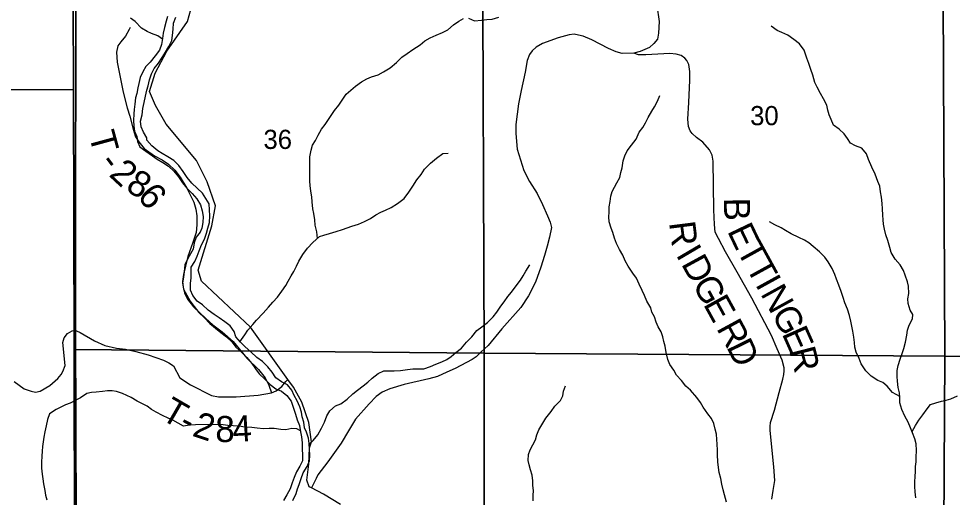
# Model space of a CAD drawing. Extents: x 2043100 to 2470832, y 443715 to 810583.
# Drawn here: x 2290243 to 2300993, y 612140 to 617648 of the extents above; entities that cross this region are included whole.
import ezdxf

# ---------------------------------------------------------------- set-up
doc = ezdxf.new("R2010")
doc.units = 0
for name, color, linetype in [('GM_X_County_Road', 7, 'Continuous'), ('GM_X_Major_River', 7, 'Continuous'), ('GM_X_Minor_River', 7, 'Continuous'), ('GM_X_Section', 7, 'Continuous'), ('GM_X_Section_Text', 7, 'Continuous'), ('GM_X_State_Route', 7, 'Continuous'), ('GM_X_Township', 7, 'Continuous'), ('GM_X_Township_Road', 7, 'Continuous'), ('GM_X_Township_Road_Text', 7, 'Continuous')]:
    doc.layers.add(name, color=color, linetype=linetype)

msp = doc.modelspace()

# ---------------------------------------------------------------- linework, layer by layer
at = {"layer": 'GM_X_County_Road'}
msp.add_lwpolyline([(2297592, 617800), (2297616, 617614), (2297611, 617482), (2297600, 617413), (2297558, 617363), (2297505, 617316), (2297399, 617271), (2297326, 617253), (2297192, 617247), (2297121, 617265), (2297035, 617304), (2296844, 617405), (2296742, 617446), (2296687, 617459), (2296639, 617471), (2296583, 617464), (2296456, 617427), (2296274, 617363), (2296203, 617321), (2296157, 617280), (2296126, 617236), (2296096, 617167), (2296074, 617033), (2296028, 616822), (2295999, 616667), (2295967, 616432), (2295969, 616326), (2295984, 616148), (2296061, 615900), (2296126, 615774), (2296211, 615637), (2296273, 615511), (2296332, 615381), (2296363, 615305), (2296377, 615245), (2296356, 615133), (2296327, 615030), (2296296, 614922), (2296256, 614787), (2296193, 614616), (2296115, 614457), (2296024, 614326), (2295805, 614078), (2295647, 613888), (2295563, 613809), (2295510, 613756), (2295464, 613724), (2295269, 613624), (2295174, 613581), (2295064, 613530), (2294966, 613503), (2294681, 613440), (2294515, 613390), (2294428, 613351), (2294360, 613299), (2294277, 613216), (2294123, 613038), (2294042, 612905), (2293958, 612762), (2293802, 612548), (2293727, 612447), (2293689, 612397), (2293669, 612358), (2293615, 612247)], dxfattribs=at)
at = {"layer": 'GM_X_Major_River'}
for points in [[(2291958, 617674), (2291942, 617619), (2291921, 617547), (2291908, 617481), (2291901, 617419), (2291889, 617352), (2291864, 617286), (2291813, 617219), (2291756, 617149), (2291706, 617098), (2291671, 617036), (2291644, 616971), (2291626, 616903), (2291617, 616853)], [(2291652, 616402), (2291647, 616470), (2291664, 616542), (2291674, 616615), (2291687, 616685), (2291704, 616757), (2291719, 616826), (2291733, 616876), (2291748, 616946), (2291773, 617013), (2291804, 617075), (2291852, 617136), (2291897, 617200), (2291934, 617261), (2291974, 617327), (2292005, 617396), (2292014, 617456), (2292023, 617526), (2292027, 617598), (2292052, 617667)], [(2291617, 616853), (2291604, 616786), (2291590, 616736), (2291579, 616666), (2291572, 616602), (2291570, 616552), (2291567, 616475), (2291570, 616411), (2291577, 616355), (2291605, 616293), (2291610, 616235), (2291640, 616172), (2291709, 616122), (2291785, 616071), (2291838, 616031), (2291902, 615994), (2291967, 615949), (2292031, 615895), (2292084, 615828), (2292128, 615758), (2292179, 615698), (2292242, 615635), (2292296, 615575), (2292335, 615506), (2292356, 615436), (2292368, 615370), (2292363, 615301), (2292354, 615237), (2292332, 615191), (2292288, 615133)], [(2291717, 616275), (2291681, 616342), (2291652, 616402)], [(2293401, 612103), (2293438, 612185), (2293454, 612236), (2293473, 612288), (2293494, 612358), (2293520, 612423), (2293565, 612493), (2293590, 612558), (2293595, 612626), (2293593, 612692), (2293586, 612760), (2293581, 612820), (2293558, 612888), (2293536, 612940), (2293527, 613004), (2293507, 613066), (2293500, 613118), (2293479, 613180), (2293449, 613249), (2293416, 613311), (2293387, 613371), (2293337, 613434), (2293270, 613468), (2293204, 613513), (2293161, 613581), (2293111, 613642), (2293050, 613704), (2292984, 613747), (2292915, 613813), (2292852, 613872), (2292796, 613924), (2292745, 613987), (2292725, 614047), (2292678, 614115), (2292617, 614160), (2292553, 614205), (2292493, 614243), (2292424, 614294), (2292360, 614356), (2292297, 614397), (2292247, 614463), (2292222, 614525), (2292221, 614599), (2292228, 614667), (2292230, 614737), (2292231, 614787), (2292270, 614852), (2292300, 614914), (2292323, 614976), (2292348, 615045), (2292381, 615111), (2292405, 615178), (2292422, 615236), (2292439, 615304), (2292444, 615379), (2292440, 615447), (2292435, 615519), (2292398, 615580), (2292358, 615640), (2292299, 615698), (2292236, 615755), (2292184, 615821), (2292139, 615888), (2292088, 615958), (2292030, 616017), (2291959, 616059), (2291895, 616098), (2291845, 616128), (2291778, 616185), (2291718, 616250), (2291717, 616275)], [(2292288, 615133), (2292264, 615068), (2292251, 614996), (2292221, 614943), (2292186, 614879), (2292157, 614814), (2292148, 614740), (2292140, 614674), (2292131, 614610), (2292142, 614536), (2292181, 614466), (2292217, 614398), (2292262, 614335), (2292319, 614265), (2292381, 614206), (2292446, 614142), (2292508, 614087), (2292569, 614037), (2292635, 613986), (2292696, 613928), (2292745, 613867), (2292811, 613806), (2292872, 613748), (2292928, 613681), (2292971, 613619), (2293014, 613559), (2293078, 613500), (2293139, 613438), (2293203, 613389), (2293268, 613362), (2293332, 613310), (2293379, 613245), (2293408, 613165), (2293430, 613097), (2293449, 613033), (2293476, 612965), (2293490, 612895), (2293499, 612835), (2293506, 612767), (2293507, 612695), (2293513, 612627), (2293510, 612561), (2293481, 612498), (2293443, 612434), (2293416, 612368), (2293391, 612305), (2293368, 612239), (2293332, 612170), (2293293, 612102)]]:
    msp.add_lwpolyline(points, dxfattribs=at)
at = {"layer": 'GM_X_Minor_River'}
for points in [[(2295423, 617653), (2295490, 617625), (2295573, 617630), (2295633, 617640), (2295693, 617644), (2295771, 617667)], [(2291900, 617413), (2291844, 617449), (2291774, 617477), (2291722, 617499), (2291658, 617540), (2291583, 617616), (2291529, 617656)], [(2293683, 615120), (2293676, 615197), (2293658, 615273), (2293653, 615335), (2293641, 615405), (2293632, 615461), (2293624, 615541), (2293617, 615599), (2293607, 615663), (2293601, 615727), (2293596, 615777), (2293596, 615844), (2293597, 615924), (2293596, 616060), (2293610, 616136), (2293627, 616192), (2293659, 616247), (2293690, 616309), (2293730, 616377), (2293771, 616430), (2293809, 616488), (2293880, 616593), (2293930, 616653), (2293977, 616720), (2294015, 616778), (2294068, 616826), (2294120, 616871), (2294190, 616921), (2294251, 616956), (2294307, 616980), (2294381, 617003), (2294445, 617037), (2294522, 617084), (2294594, 617142), (2294655, 617205), (2294715, 617249), (2294783, 617294), (2294864, 617349), (2294920, 617393), (2294981, 617427), (2295049, 617458), (2295123, 617488), (2295183, 617521), (2295250, 617579), (2295312, 617618), (2295366, 617650)], [(2300195, 615335), (2300191, 615387), (2300189, 615461), (2300184, 615523), (2300178, 615593), (2300167, 615657), (2300157, 615719), (2300136, 615773), (2300104, 615859), (2300067, 615939), (2300029, 616029), (2300004, 616093), (2299952, 616159), (2299878, 616184), (2299820, 616216), (2299787, 616270), (2299747, 616324), (2299691, 616378), (2299624, 616423), (2299596, 616489), (2299574, 616543), (2299559, 616595), (2299547, 616651), (2299508, 616725), (2299476, 616787), (2299437, 616861), (2299411, 616915), (2299385, 616999), (2299364, 617065), (2299342, 617133), (2299319, 617195), (2299287, 617287), (2299232, 617360), (2299168, 617408), (2299100, 617458), (2299029, 617489), (2298977, 617513), (2298907, 617563)], [(2298392, 612084), (2298371, 612170), (2298355, 612224), (2298338, 612292), (2298326, 612356), (2298310, 612424), (2298299, 612484), (2298293, 612548), (2298290, 612628), (2298290, 612684), (2298285, 612750), (2298283, 612806), (2298276, 612866), (2298264, 612924), (2298248, 612988), (2298219, 613048), (2298177, 613102), (2298126, 613176), (2298092, 613232), (2298050, 613290), (2297979, 613371), (2297925, 613419), (2297876, 613485), (2297818, 613547), (2297788, 613604), (2297739, 613670), (2297719, 613726), (2297698, 613806), (2297688, 613878), (2297673, 613934), (2297659, 613988), (2297641, 614046), (2297606, 614100), (2297584, 614154), (2297564, 614218), (2297535, 614270), (2297521, 614322), (2297476, 614396), (2297448, 614462), (2297420, 614518), (2297387, 614592), (2297357, 614660), (2297316, 614719), (2297262, 614799), (2297227, 614861), (2297199, 614927), (2297159, 614993), (2297128, 615059), (2297104, 615123), (2297083, 615187), (2297063, 615239), (2297040, 615309), (2297038, 615369), (2297042, 615423), (2297043, 615481), (2297053, 615545), (2297062, 615607), (2297078, 615658), (2297102, 615710), (2297129, 615760), (2297163, 615820), (2297178, 615879), (2297192, 615931), (2297203, 616013), (2297221, 616069), (2297251, 616126), (2297298, 616192), (2297352, 616260), (2297389, 616341), (2297430, 616395), (2297460, 616449), (2297492, 616510), (2297535, 616582), (2297565, 616632), (2297600, 616697), (2297624, 616765)], [(2292790, 613931), (2292847, 614009), (2292881, 614064), (2292940, 614130), (2292980, 614180), (2293057, 614259), (2293121, 614330), (2293168, 614384), (2293224, 614443), (2293275, 614511), (2293321, 614577), (2293348, 614628), (2293382, 614690), (2293410, 614740), (2293443, 614799), (2293469, 614857), (2293516, 614933), (2293568, 615006), (2293631, 615072), (2293705, 615141), (2293756, 615157), (2293822, 615174), (2293898, 615198), (2293970, 615221), (2294026, 615241), (2294081, 615260), (2294157, 615284), (2294225, 615313), (2294293, 615349), (2294354, 615390), (2294412, 615420), (2294466, 615446), (2294533, 615475), (2294605, 615523), (2294681, 615578), (2294736, 615650), (2294780, 615719), (2294829, 615793), (2294877, 615856), (2294916, 615916), (2294986, 615987), (2295053, 616043), (2295125, 616096), (2295189, 616102)], [(2300388, 613301), (2300305, 613346), (2300241, 613420), (2300191, 613460), (2300136, 613485), (2300060, 613533), (2299996, 613597), (2299943, 613676), (2299919, 613736), (2299884, 613812), (2299870, 613866), (2299866, 613922), (2299859, 613982), (2299847, 614050), (2299834, 614110), (2299824, 614166), (2299808, 614232), (2299785, 614304), (2299757, 614378), (2299736, 614440), (2299712, 614508), (2299687, 614582), (2299659, 614652), (2299640, 614704), (2299610, 614772), (2299565, 614848), (2299525, 614902), (2299465, 614964), (2299392, 615027), (2299340, 615067), (2299290, 615099), (2299224, 615130), (2299138, 615172), (2299073, 615212), (2299023, 615241), (2298951, 615275), (2298889, 615311)], [(2300574, 612134), (2300565, 612204), (2300561, 612266), (2300562, 612320), (2300564, 612376), (2300567, 612442), (2300569, 612494), (2300575, 612549), (2300578, 612601), (2300580, 612679), (2300577, 612755), (2300563, 612811), (2300536, 612883), (2300512, 612939), (2300486, 613005), (2300445, 613073), (2300413, 613151), (2300390, 613227), (2300390, 613289), (2300383, 613343), (2300371, 613405), (2300362, 613475), (2300358, 613531), (2300357, 613599), (2300369, 613655), (2300393, 613729), (2300416, 613794), (2300434, 613852), (2300455, 613926), (2300469, 614004), (2300478, 614065), (2300496, 614121), (2300535, 614193), (2300537, 614243), (2300508, 614295), (2300486, 614369), (2300482, 614423), (2300491, 614485), (2300489, 614569), (2300478, 614621), (2300450, 614697), (2300429, 614749), (2300391, 614815), (2300335, 614881), (2300288, 614957), (2300274, 615015), (2300251, 615097), (2300229, 615159), (2300210, 615225), (2300202, 615283), (2300195, 615335)], [(2293587, 612752), (2293635, 612794), (2293689, 612857), (2293728, 612935), (2293765, 613006), (2293793, 613078), (2293825, 613136), (2293892, 613193), (2293952, 613215), (2294025, 613270), (2294089, 613330), (2294145, 613373), (2294210, 613423), (2294262, 613465), (2294315, 613510), (2294381, 613564), (2294449, 613595), (2294503, 613595), (2294567, 613594), (2294641, 613600), (2294720, 613611), (2294780, 613619), (2294850, 613618), (2294908, 613618), (2294984, 613646), (2295046, 613671), (2295115, 613699), (2295171, 613726), (2295223, 613760), (2295275, 613805), (2295342, 613855), (2295400, 613924), (2295459, 613986), (2295517, 614059), (2295576, 614103), (2295642, 614150), (2295707, 614218), (2295749, 614270), (2295796, 614339), (2295832, 614389), (2295875, 614450), (2295919, 614500), (2295971, 614572), (2296022, 614637), (2296052, 614687), (2296083, 614743), (2296127, 614814)], [(2293488, 612905), (2293444, 612927), (2293388, 612931), (2293318, 612916), (2293263, 612922), (2293183, 612930), (2293129, 612931), (2293063, 612929), (2292989, 612934), (2292927, 612942), (2292849, 612947), (2292781, 612957), (2292711, 612963), (2292653, 612968), (2292599, 612974), (2292547, 612976), (2292281, 612974), (2292211, 612969), (2292141, 612957), (2292079, 612995), (2292019, 613028), (2291963, 613052), (2291899, 613082), (2291826, 613121), (2291774, 613151), (2291722, 613189), (2291668, 613216), (2291606, 613248), (2291539, 613288), (2291489, 613311), (2291437, 613333), (2291371, 613357), (2291319, 613364), (2291267, 613364), (2291207, 613356), (2291137, 613351), (2291081, 613345), (2291030, 613336), (2290956, 613286), (2290902, 613259), (2290837, 613225), (2290783, 613203), (2290727, 613176), (2290675, 613150), (2290600, 613099), (2290576, 613037), (2290561, 612963), (2290545, 612893), (2290534, 612832), (2290524, 612778), (2290518, 612724), (2290515, 612670), (2290509, 612614), (2290508, 612544), (2290508, 612476), (2290515, 612406), (2290521, 612351), (2290531, 612295), (2290544, 612217), (2290554, 612165), (2290567, 612109)], [(2296166, 612100), (2296167, 612160), (2296171, 612220), (2296164, 612274), (2296162, 612328), (2296156, 612394), (2296135, 612456), (2296119, 612512), (2296110, 612562), (2296114, 612632), (2296134, 612688), (2296163, 612743), (2296195, 612801), (2296208, 612857), (2296232, 612915), (2296277, 612994), (2296313, 613050), (2296374, 613129), (2296418, 613189), (2296483, 613253), (2296509, 613308), (2296515, 613360), (2296540, 613424)], [(2300530, 612897), (2300568, 612965), (2300607, 613026), (2300655, 613088), (2300704, 613158), (2300742, 613209), (2300802, 613227), (2300870, 613246), (2300921, 613258), (2300975, 613274), (2301051, 613307)]]:
    msp.add_lwpolyline(points, dxfattribs=at)
at = {"layer": 'GM_X_Section'}
for points in [[(2290863, 622088), (2290868, 618859), (2290874, 616830), (2285514, 616857), (2285518, 622176)], [(2290868, 618859), (2295311, 618781), (2295585, 618781), (2295602, 613799), (2290884, 613839), (2290874, 616830)], [(2300882, 618700), (2300907, 613765), (2295602, 613799), (2295585, 618781), (2300644, 618693)], [(2306313, 618670), (2306256, 613737), (2300907, 613765), (2300882, 618700), (2306045, 618668)], [(2285514, 616857), (2290874, 616830), (2290884, 613839), (2290886, 611512), (2285545, 611578)], [(2295602, 613799), (2295598, 608504), (2290882, 608528), (2290886, 611512), (2290884, 613839)], [(2295602, 613799), (2300907, 613765), (2300875, 608468), (2295598, 608504)], [(2300907, 613765), (2306256, 613737), (2306198, 608430), (2300875, 608468)]]:
    msp.add_lwpolyline(points, close=True, dxfattribs=at)
at = {"layer": 'GM_X_State_Route'}
msp.add_lwpolyline([(2293949, 612057), (2293754, 612176), (2293615, 612247), (2293586, 612262), (2293560, 612338), (2293585, 612521), (2293591, 612710), (2293614, 612778), (2293584, 613002), (2293504, 613236), (2293407, 613408), (2293344, 613496), (2292913, 614097), (2292347, 614628), (2292311, 614753), (2292469, 615263), (2292508, 615493), (2292412, 615770), (2292292, 616015), (2291941, 616434), (2291819, 616650), (2291750, 616810), (2291814, 617021), (2291948, 617274), (2292186, 617617), (2292243, 617821)], dxfattribs=at)
at = {"layer": 'GM_X_Township'}
for points in [[(2309929, 582079), (2307256, 582122), (2303069, 582188), (2302644, 582195), (2297884, 582270), (2291370, 582373), (2290742, 582400), (2290718, 585069), (2290786, 589239), (2290846, 592873), (2290885, 606181), (2290909, 610789), (2290899, 614059), (2290900, 618867), (2291836, 618850), (2297254, 618753), (2300671, 618691), (2300679, 619574), (2300717, 624094), (2303048, 624077), (2305185, 624062), (2306890, 624048), (2310832, 624022)], [(2274753, 606478), (2274796, 611478), (2274797, 611586), (2280132, 611578), (2280135, 612298), (2280174, 622203), (2282304, 622194), (2290886, 622083), (2290876, 619364), (2290900, 618867), (2290899, 614059), (2290909, 610789), (2290885, 606181)]]:
    msp.add_lwpolyline(points, dxfattribs=at)
at = {"layer": 'GM_X_Township_Road'}
for points in [[(2291526, 617547), (2291514, 617522), (2291472, 617447), (2291419, 617382), (2291386, 617334), (2291371, 617263), (2291379, 617147), (2291445, 616804), (2291494, 616624), (2291523, 616528), (2291562, 616378), (2291590, 616289), (2291627, 616229), (2291690, 616156), (2291807, 616070), (2291896, 616025), (2291967, 615974), (2292042, 615903), (2292104, 615826), (2292180, 615697), (2292261, 615536), (2292282, 615456), (2292293, 615378), (2292293, 615274), (2292285, 615188), (2292249, 615071), (2292191, 614913), (2292141, 614704), (2292130, 614624), (2292136, 614558), (2292153, 614494), (2292188, 614422), (2292255, 614331), (2292398, 614197), (2292479, 614124), (2292586, 614046), (2292712, 613932), (2292870, 613740), (2293004, 613610), (2293082, 613513), (2293125, 613432), (2293154, 613342)], [(2298914, 612120), (2298931, 612218), (2298950, 612333), (2298939, 612491), (2298897, 612907), (2298894, 612955), (2298898, 612999), (2298944, 613144), (2299000, 613347), (2299041, 613500), (2299052, 613554), (2299058, 613594), (2299055, 613628), (2299035, 613720), (2298975, 613850), (2298912, 614002), (2298683, 614431), (2298515, 614730), (2298382, 614965), (2298299, 615117), (2298264, 615190), (2298253, 615279), (2298247, 615449), (2298240, 616008), (2298227, 616076), (2298197, 616138), (2298122, 616226), (2298049, 616281), (2297999, 616325), (2297974, 616358), (2297956, 616408), (2297949, 616491), (2297959, 616685), (2297971, 616940), (2297970, 617040), (2297961, 617122), (2297936, 617166), (2297914, 617194), (2297872, 617224), (2297812, 617241), (2297740, 617248), (2297464, 617234), (2297378, 617233), (2297326, 617253)], [(2290192, 613471), (2290306, 613389), (2290386, 613362), (2290438, 613351), (2290490, 613362), (2290601, 613428), (2290696, 613509), (2290733, 613554), (2290750, 613588), (2290779, 613658), (2290753, 613921), (2290769, 613976), (2290804, 614026), (2290858, 614057), (2290899, 614059), (2290908, 614055)], [(2290908, 614055), (2290953, 614036), (2291115, 613940), (2291237, 613886), (2291369, 613858), (2291473, 613845), (2291592, 613817), (2291735, 613778), (2291909, 613719), (2291974, 613687), (2292026, 613654), (2292098, 613513), (2292223, 613435), (2292465, 613310), (2292545, 613296), (2292747, 613297), (2292999, 613317), (2293154, 613342), (2293208, 613367), (2293273, 613416), (2293320, 613473), (2293344, 613496)]]:
    msp.add_lwpolyline(points, dxfattribs=at)

# ---------------------------------------------------------------- texts
at = {"layer": 'GM_X_Section_Text'}
for s, p in [('30', (2298665, 616422)), ('36', (2293062, 616149))]:
    msp.add_text(s, height=220.8, rotation=0, dxfattribs=at).set_placement(p)
at = {"layer": 'GM_X_Township_Road_Text'}
for s, rotation, p in [('T', 285.2525, (2291048, 616313)), ('-', 306.8272, (2291160, 615987)), ('2', 317.0089, (2291273, 615845)), ('8', 328.6214, (2291461, 615679)), ('6', 310.1407, (2291599, 615599)), ('B', 270.9173, (2298362, 615587)), ('R', 277.2122, (2297731, 615301)), ('E', 295.4708, (2298397, 615205)), ('T', 298.8815, (2298503, 614985)), ('I', 300.4643, (2297805, 614932)), ('D', 298.5709, (2297866, 614828)), ('T', 298.7811, (2298611, 614789)), ('G', 298.7843, (2297993, 614595)), ('I', 298.7824, (2298719, 614592)), ('N', 298.7698, (2298779, 614484)), ('E', 298.7879, (2298120, 614363)), ('G', 297.7267, (2298905, 614254)), ('R', 298.461, (2298272, 614086)), ('E', 294.0382, (2299026, 614025)), ('D', 296.1138, (2298388, 613872)), ('R', 284.3723, (2299113, 613832)), ('T', 329.9006, (2291865, 613048)), ('2', 341.7368, (2292230, 612850)), ('8', 359.8454, (2292507, 612776)), ('4', 3.3172, (2292711, 612776)), ('-', 332.3086, (2292071, 612928))]:
    msp.add_text(s, height=300, rotation=rotation, dxfattribs=at).set_placement(p)

doc.saveas('drawing.dxf')
